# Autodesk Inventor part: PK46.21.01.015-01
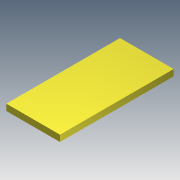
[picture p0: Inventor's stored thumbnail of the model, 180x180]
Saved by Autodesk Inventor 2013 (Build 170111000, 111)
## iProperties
Created: 2005-04
Part Number: PK46.21.01.015-01
Material: Steel, Mild
Document SubType Name: Modeling
Designer: salex
Manufacturer: Standard
Standards Organization: Custom
Density: 7.86 g/cm^3
Author: salex
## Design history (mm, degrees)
sketch "Эскиз1"
  geometry: L1 (0, 0)-(85, 0); L2 (85, 0)-(85, 180); L3 (85, 180)-(0, 180); L4 (0, 180)-(0, 0)
  constraints: 8 end point, 2 parallel, 1 horizontal, 1 perpendicular, 1 other
  dimensions: "d0" = 180 distance of L3.end L1.start; "d1" = 85 distance of L1.start L1.end
extrude "Выдавливание1" new body sketch "Эскиз1" distance "d2" = 10; taper "d3" = 0 deg
body "Solid1"
